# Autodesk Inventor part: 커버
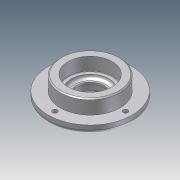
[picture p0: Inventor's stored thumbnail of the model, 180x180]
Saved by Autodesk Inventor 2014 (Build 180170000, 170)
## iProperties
Company: 한국ATC센터
Created: 2014-10
Part Number: 커버
Document SubType Name: Modeling
Designer: KYOUNG IL JANG
Density: 1 g/cm^3
Mass: 44.7286 g
Surface Area: 161.165 cm^2
Volume: 44.7286 cm^3
Material: Generic
Appearance: Default
Author: KYOUNG IL JANG
Revision Number: 1
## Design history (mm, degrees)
sketch "스케치1"
  geometry: C1 r 38 at (0, 0); 1 further point
  constraints: 1 centre point, 1 coincident
  dimensions: "d0" = 76 diameter of C1
extrude "돌출1" new body sketch "스케치1" distance "d1" = 7; taper "d2" = 0 deg
sketch "스케치2"
  geometry: C1 r 27 at (0, 0); 1 further point
  constraints: 1 centre point, 1 coincident
  dimensions: "d3" = 54 diameter of C1
extrude "돌출2" join sketch "스케치2" distance "d4" = 13; taper "d5" = 0 deg
sketch "스케치3"
  geometry: C1 r 20 at (0, 0); 1 further point
  constraints: 1 centre point, 1 coincident
  dimensions: "d6" = 40 diameter of C1
extrude "돌출3" join sketch "스케치3" distance "d7" = 5; taper "d8" = 0 deg
hole "구멍1" diameter "d11" = 25; stored, may be unused: countersink angle "d15" = 90 deg, drill point angle "d17" = 118 deg; dims "d9" = 10, "d10" = 10, "d12" = 6, "d13" = 32, "d14" = 8.3, "d16" = 8
hole "구멍2" diameter "d20" = 34; stored, may be unused: countersink angle "d24" = 90 deg, drill point angle "d26" = 0 deg; dims "d18" = 10, "d19" = 10, "d21" = 6, "d22" = 40, "d23" = 12, "d25" = 3
fillet "모깎기2" dims "d34" = 3
fillet "모깎기1" dims "d27" = 0.3
chamfer "모따기1" distance "d28" = 1; stored, may be unused: second distance "d29" = 2, angle "d30" = 45 deg
chamfer "모따기2" distance "d31" = 1.2; stored, may be unused: second distance "d32" = 2, angle "d33" = 30 deg
sketch "스케치4" dims "d35" = 64
  geometry: 3 further points
  constraints: 2 horizontal alignment, 1 coincident, 2 other
hole "구멍3" sketch "스케치4" diameter "d36" = 4.5; stored, may be unused: countersink angle "d40" = 90 deg, drill point angle "d42" = 118 deg; dims "d37" = 6, "d38" = 8, "d39" = 4.4, "d41" = 13
node "솔리드1"
pattern_circular "원형 패턴1" dims angle "d44" = 360 deg
